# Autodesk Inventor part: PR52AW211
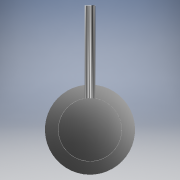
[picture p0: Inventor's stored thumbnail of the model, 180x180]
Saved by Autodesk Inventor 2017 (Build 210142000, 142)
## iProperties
Created: 2021-04
Part Number: PR52AW211
Material: Generico
Document SubType Name: Modeling
Designer: PIZZERA
Density: 1 g/cm^3
Appearance: Default
Author: PIZZERA
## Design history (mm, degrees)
feature "Base2"
node "Solido1"
node "Solido3"
